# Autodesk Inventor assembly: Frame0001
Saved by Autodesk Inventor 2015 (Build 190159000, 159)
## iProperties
Created: 2020-03
Part Number: Frame0001
Document SubType Name: Assembly
Designer: 徐冠倫
Mass: 2422.11 g
Surface Area: 2063.16 cm^2
Volume: 308.549 cm^3
Density: 7.85 g/cm^3
_FrameDoc: Frame Assembly
_Version: 15.0.0
Author: 徐冠倫
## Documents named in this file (4)
- C:\Users\徐冠倫\Desktop\Topic 13-3_框架分析(銷約束)\Topic 13-3_框架分析(銷約束)\Frame\Frame0001.iam
- C:\Users\徐冠倫\Desktop\Topic 13-3_框架分析(銷約束)\Topic 13-3_框架分析(銷約束)\Frame\Skeleton0001.ipt
- C:\Users\徐冠倫\Desktop\Topic 13-3_框架分析(銷約束)\Topic 13-3_框架分析(銷約束)\Frame\ISO 30x30x3 00000001.ipt
- ISO 30x30x3 00000001.ipt
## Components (2 placed, 2 different names)
1. Frame Reference Model
2. ISO 30x30x3 00000001:1
